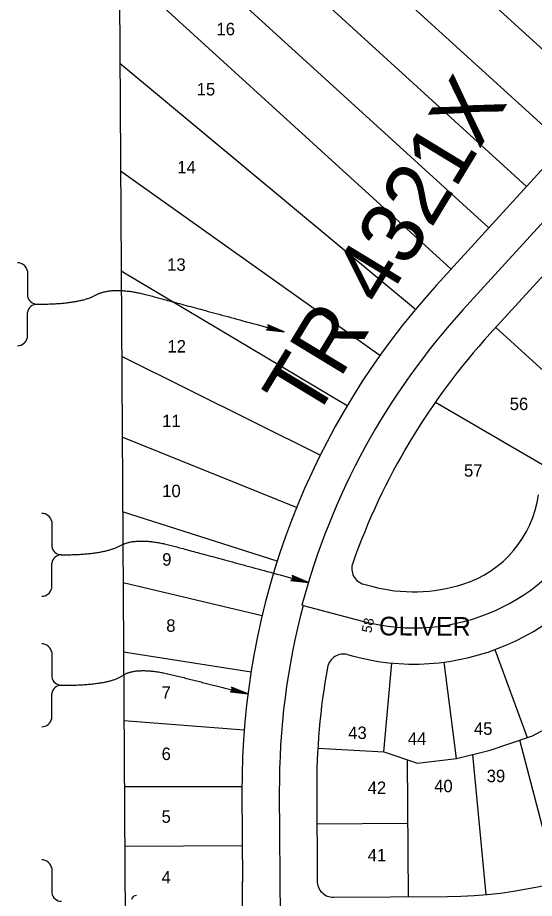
# Model space of a CAD drawing. Extents: x 6387474 to 6390971, y 1972046 to 1973920.
# Drawn here: x 6388992 to 6389408, y 1972544 to 1973251 of the extents above; entities that cross this region are included whole.
import ezdxf

# ---------------------------------------------------------------- set-up
doc = ezdxf.new("R2010")
doc.units = 0
for name, color, linetype in [('1', 7, 'Continuous'), ('2', 7, 'Continuous'), ('3', 7, 'Continuous'), ('4', 7, 'Continuous'), ('7', 7, 'Continuous'), ('8', 7, 'Continuous')]:
    doc.layers.add(name, color=color, linetype=linetype)

msp = doc.modelspace()

# ---------------------------------------------------------------- linework, layer by layer
at = {"layer": '1'}
msp.add_line((6389072.58, 1973552.73), (6389079.62, 1972388), dxfattribs=at)
at = {"layer": '2'}
for p, q in [((6389350.37, 1973016.66), (6389456.72, 1973133.37)), ((6389221.81, 1972779.1), (6389220.84, 1972779.36)), ((6389221.81, 1972779.1), (6389269.5, 1972766.4)), ((6389202.67, 1972629.26), (6389204.12, 1972388.75))]:
    msp.add_line(p, q, dxfattribs=at)
for centre, radius, start, end in [((6389335.56, 1972901.3), 388, 270.34667, 18.92365), ((6389771.66, 1972632.72), 570, 137.65572, 165.09236), ((6389310.66, 1972921.02), 160, 255.09194, 332.86738), ((6389771.66, 1972632.71), 569, 165.09129, 180.34667)]:
    msp.add_arc(centre, radius, start, end, dxfattribs=at)
at = {"layer": '3'}
for p, q in [((6389461.63, 1973182.31), (6389072.67, 1973536.78)), ((6389431.59, 1973148.83), (6389073.04, 1973475.59)), ((6389401.27, 1973115.57), (6389073.41, 1973414.37)), ((6389370.96, 1973082.31), (6389073.78, 1973353.15)), ((6389340.65, 1973049.05), (6389074.15, 1973291.92)), ((6389311.98, 1973016.76), (6389074.62, 1973214.19)), ((6389283.44, 1972979.77), (6389075.15, 1973127.84)), ((6389257.09, 1972939.34), (6389075.63, 1973047.48)), ((6389435.19, 1972948.92), (6389376.6, 1973002.32)), ((6389235.43, 1972899.65), (6389076.05, 1972978.99)), ((6389327.99, 1972942.3), (6389414.18, 1972892.32)), ((6389216.48, 1972857.61), (6389076.44, 1972914.35)), ((6389200.96, 1972814.66), (6389076.8, 1972854.25)), ((6389188.79, 1972770.79), (6389077.15, 1972797.26)), ((6389077.48, 1972741.93), (6389180.01, 1972725.8)), ((6389375.73, 1972743.57), (6389401.65, 1972672.9)), ((6389286.52, 1972661.43), (6389293.16, 1972732.83)), ((6389345.1, 1972656.26), (6389335.04, 1972733.6)), ((6389406.07, 1972674.39), (6389449.77, 1972698.35)), ((6389077.82, 1972686.64), (6389174.5, 1972679.13)), ((6389371.93, 1972662.88), (6389406.07, 1972674.39)), ((6389425.58, 1972556.87), (6389395.79, 1972670.93)), ((6389233.6, 1972664.57), (6389286.52, 1972661.43)), ((6389286.52, 1972661.43), (6389313.75, 1972652.36)), ((6389345.1, 1972656.26), (6389371.93, 1972662.88)), ((6389305.46, 1972655.12), (6389306.13, 1972545.12)), ((6389313.75, 1972652.36), (6389345.1, 1972656.26)), ((6389368.72, 1972546.86), (6389358.18, 1972659.49)), ((6389078.14, 1972633.77), (6389172.66, 1972633.63)), ((6389232.82, 1972603.68), (6389305.77, 1972604.12)), ((6389078.43, 1972585.83), (6389172.92, 1972586.4))]:
    msp.add_line(p, q, dxfattribs=at)
at = {"layer": '4'}
for p, q in [((6389328.93, 1973036.19), (6389435.29, 1973152.9)), ((6389371.8, 1972997.13), (6389418.21, 1973048.05)), ((6389270.51, 1972796.15), (6389276.96, 1972794.43)), ((6389257.52, 1972739.58), (6389262.04, 1972738.38)), ((6389172.67, 1972629.1), (6389173.1, 1972556.84)), ((6389232.67, 1972629.45), (6389233.1, 1972557.68)), ((6389246.18, 1972544.76), (6389337.72, 1972545.31))]:
    msp.add_line(p, q, dxfattribs=at)
for centre, radius, start, end in [((6389771.66, 1972632.72), 599, 137.65605, 180.34667), ((6389335.56, 1972901.3), 356, 270.34667, 18.92365), ((6389771.66, 1972632.72), 541, 137.65572, 160.52995), ((6389323.62, 1972880.02), 88, 287.54705, 352.08944), ((6389310.66, 1972921.02), 189, 253.67626, 332.86738), ((6389273.85, 1972808.71), 13, 160.52995, 255.09194), ((6389310.66, 1972921.02), 131, 255.09194, 287.55198), ((6389254.18, 1972727.02), 13, 75.09194, 169.67106), ((6389771.66, 1972632.71), 539, 169.67106, 180.34667), ((6388172.12, 1972551.26), 1001, 357.80051, 0.34648), ((6389246.1, 1972557.76), 13, 180.34667, 270.34667)]:
    msp.add_arc(centre, radius, start, end, dxfattribs=at)
at = {"layer": '8'}
for p, q in [((6389000.34, 1973047.64), (6389000.34, 1973027.66)), ((6389000.34, 1972994.35), (6389000.34, 1973014.33)), ((6389192.47, 1973000.46), (6389206.51, 1972998.74)), ((6389206.51, 1972998.74), (6389193.52, 1973004.32)), ((6389019.82, 1972846.37), (6389019.82, 1972826.39)), ((6389019.82, 1972793.09), (6389019.82, 1972813.07)), ((6389225.99, 1972797.47), (6389213, 1972803.06)), ((6389211.95, 1972799.19), (6389225.99, 1972797.47)), ((6389019.82, 1972741.6), (6389019.82, 1972721.62)), ((6389163.36, 1972709.58), (6389177.43, 1972708.17)), ((6389177.43, 1972708.17), (6389164.32, 1972713.47)), ((6389019.82, 1972688.32), (6389019.82, 1972708.3)), ((6389019.82, 1972568.13), (6389019.82, 1972548.15))]:
    msp.add_line(p, q, dxfattribs=at)
for points in [[(6389008.23, 1973020.99), (6389009.5, 1973020.99), (6389010.76, 1973021), (6389012, 1973021.02), (6389013.23, 1973021.03), (6389014.45, 1973021.06), (6389015.65, 1973021.09), (6389016.83, 1973021.12), (6389018, 1973021.16), (6389019.16, 1973021.21), (6389020.3, 1973021.26), (6389021.42, 1973021.31), (6389022.54, 1973021.37), (6389023.63, 1973021.44), (6389024.72, 1973021.51), (6389025.79, 1973021.59), (6389026.84, 1973021.67), (6389027.88, 1973021.76), (6389028.9, 1973021.85), (6389029.91, 1973021.95), (6389030.91, 1973022.06), (6389031.89, 1973022.16), (6389032.86, 1973022.28), (6389033.81, 1973022.4), (6389034.75, 1973022.52), (6389035.67, 1973022.65), (6389036.58, 1973022.79), (6389037.48, 1973022.93), (6389038.35, 1973023.08), (6389039.22, 1973023.23), (6389040.07, 1973023.38), (6389040.91, 1973023.55), (6389041.73, 1973023.71), (6389042.54, 1973023.89), (6389043.33, 1973024.07), (6389044.11, 1973024.25), (6389044.87, 1973024.44), (6389045.62, 1973024.63), (6389046.35, 1973024.83), (6389047.07, 1973025.04), (6389047.78, 1973025.25), (6389048.47, 1973025.46), (6389049.15, 1973025.68), (6389049.81, 1973025.91), (6389050.46, 1973026.14), (6389051.09, 1973026.38), (6389051.71, 1973026.62), (6389052.31, 1973026.87), (6389052.9, 1973027.12), (6389053.47, 1973027.38), (6389054.03, 1973027.64), (6389054.58, 1973027.91), (6389055.11, 1973028.18), (6389055.63, 1973028.46), (6389056.14, 1973028.74), (6389056.67, 1973029), (6389057.21, 1973029.26), (6389057.76, 1973029.5), (6389058.32, 1973029.73), (6389058.89, 1973029.95), (6389059.47, 1973030.16), (6389060.07, 1973030.36), (6389060.67, 1973030.55), (6389061.29, 1973030.73), (6389061.92, 1973030.9), (6389062.56, 1973031.05), (6389063.21, 1973031.2), (6389063.87, 1973031.33), (6389064.55, 1973031.45), (6389065.23, 1973031.56), (6389065.93, 1973031.66), (6389066.64, 1973031.75), (6389067.36, 1973031.83), (6389068.09, 1973031.9), (6389068.83, 1973031.95), (6389069.58, 1973032), (6389070.35, 1973032.03), (6389071.12, 1973032.06), (6389071.91, 1973032.07), (6389072.71, 1973032.07), (6389073.52, 1973032.06), (6389074.34, 1973032.04), (6389075.18, 1973032.01), (6389076.02, 1973031.97), (6389076.88, 1973031.91), (6389077.74, 1973031.85), (6389078.62, 1973031.77), (6389079.51, 1973031.68), (6389080.41, 1973031.59), (6389081.33, 1973031.48), (6389082.25, 1973031.36), (6389083.18, 1973031.23), (6389084.13, 1973031.09), (6389085.09, 1973030.93), (6389086.06, 1973030.77), (6389087.04, 1973030.59), (6389088.03, 1973030.41), (6389089.04, 1973030.21), (6389090.05, 1973030), (6389091.08, 1973029.79), (6389092.11, 1973029.56)], [(6389092.11, 1973029.56), (6389093.16, 1973029.32), (6389094.22, 1973029.06), (6389095.29, 1973028.8), (6389096.38, 1973028.53), (6389097.47, 1973028.24), (6389098.58, 1973027.95), (6389099.71, 1973027.64), (6389100.87, 1973027.33), (6389102.07, 1973027), (6389103.3, 1973026.67), (6389104.57, 1973026.32), (6389105.87, 1973025.97), (6389107.21, 1973025.61), (6389108.59, 1973025.23), (6389109.99, 1973024.85), (6389111.44, 1973024.46), (6389112.91, 1973024.06), (6389114.43, 1973023.65), (6389115.97, 1973023.23), (6389117.56, 1973022.8), (6389119.18, 1973022.37), (6389120.83, 1973021.92), (6389122.51, 1973021.46), (6389124.24, 1973021), (6389125.99, 1973020.52), (6389127.79, 1973020.04), (6389129.61, 1973019.54), (6389131.48, 1973019.04), (6389133.37, 1973018.52), (6389135.3, 1973018), (6389137.27, 1973017.47), (6389139.27, 1973016.93), (6389141.31, 1973016.37), (6389143.38, 1973015.81), (6389145.49, 1973015.24), (6389147.63, 1973014.66), (6389149.8, 1973014.08), (6389152.01, 1973013.48), (6389154.26, 1973012.87), (6389156.54, 1973012.25), (6389158.86, 1973011.62), (6389161.21, 1973010.99), (6389163.59, 1973010.34), (6389166.01, 1973009.69), (6389168.47, 1973009.02), (6389170.96, 1973008.35), (6389173.48, 1973007.67), (6389176.05, 1973006.97), (6389178.64, 1973006.27), (6389181.27, 1973005.56), (6389183.93, 1973004.84), (6389186.63, 1973004.11), (6389189.37, 1973003.37), (6389192.14, 1973002.62), (6389194.94, 1973001.86), (6389197.78, 1973001.09), (6389200.66, 1973000.31), (6389203.57, 1972999.53), (6389206.51, 1972998.73)], [(6389027.71, 1972819.73), (6389028.98, 1972819.73), (6389030.24, 1972819.74), (6389031.48, 1972819.75), (6389032.71, 1972819.77), (6389033.92, 1972819.79), (6389035.12, 1972819.82), (6389036.31, 1972819.86), (6389037.48, 1972819.9), (6389038.63, 1972819.94), (6389039.77, 1972819.99), (6389040.9, 1972820.05), (6389042.01, 1972820.11), (6389043.11, 1972820.18), (6389044.19, 1972820.25), (6389045.26, 1972820.32), (6389046.32, 1972820.41), (6389047.36, 1972820.49), (6389048.38, 1972820.59), (6389049.39, 1972820.69), (6389050.39, 1972820.79), (6389051.37, 1972820.9), (6389052.34, 1972821.01), (6389053.29, 1972821.13), (6389054.23, 1972821.26), (6389055.15, 1972821.39), (6389056.06, 1972821.52), (6389056.95, 1972821.66), (6389057.83, 1972821.81), (6389058.7, 1972821.96), (6389059.55, 1972822.12), (6389060.38, 1972822.28), (6389061.21, 1972822.45), (6389062.01, 1972822.62), (6389062.81, 1972822.8), (6389063.58, 1972822.98), (6389064.35, 1972823.17), (6389065.1, 1972823.37), (6389065.83, 1972823.57), (6389066.55, 1972823.77), (6389067.26, 1972823.98), (6389067.95, 1972824.2), (6389068.62, 1972824.42), (6389069.28, 1972824.64), (6389069.93, 1972824.87), (6389070.57, 1972825.11), (6389071.18, 1972825.35), (6389071.79, 1972825.6), (6389072.38, 1972825.85), (6389072.95, 1972826.11), (6389073.51, 1972826.37), (6389074.06, 1972826.64), (6389074.59, 1972826.92), (6389075.1, 1972827.19), (6389075.62, 1972827.47), (6389076.15, 1972827.74), (6389076.68, 1972827.99), (6389077.23, 1972828.23), (6389077.79, 1972828.47), (6389078.37, 1972828.69), (6389078.95, 1972828.9), (6389079.54, 1972829.1), (6389080.15, 1972829.29), (6389080.77, 1972829.46), (6389081.4, 1972829.63), (6389082.04, 1972829.78), (6389082.69, 1972829.93), (6389083.35, 1972830.06), (6389084.02, 1972830.18), (6389084.71, 1972830.3), (6389085.41, 1972830.4), (6389086.11, 1972830.49), (6389086.83, 1972830.56), (6389087.56, 1972830.63), (6389088.31, 1972830.69), (6389089.06, 1972830.73), (6389089.82, 1972830.77), (6389090.6, 1972830.79), (6389091.39, 1972830.8), (6389092.19, 1972830.8), (6389093, 1972830.79), (6389093.82, 1972830.77), (6389094.65, 1972830.74), (6389095.5, 1972830.7), (6389096.35, 1972830.65), (6389097.22, 1972830.58), (6389098.1, 1972830.51), (6389098.99, 1972830.42), (6389099.89, 1972830.32), (6389100.8, 1972830.21), (6389101.73, 1972830.09), (6389102.66, 1972829.96), (6389103.61, 1972829.82), (6389104.57, 1972829.67), (6389105.54, 1972829.5), (6389106.52, 1972829.33), (6389107.51, 1972829.14), (6389108.51, 1972828.95), (6389109.53, 1972828.74), (6389110.55, 1972828.52), (6389111.59, 1972828.29)], [(6389111.59, 1972828.29), (6389112.64, 1972828.05), (6389113.7, 1972827.8), (6389114.77, 1972827.53), (6389115.85, 1972827.26), (6389116.95, 1972826.98), (6389118.05, 1972826.68), (6389119.18, 1972826.37), (6389120.35, 1972826.06), (6389121.55, 1972825.73), (6389122.78, 1972825.4), (6389124.05, 1972825.06), (6389125.35, 1972824.7), (6389126.69, 1972824.34), (6389128.06, 1972823.97), (6389129.47, 1972823.59), (6389130.91, 1972823.2), (6389132.39, 1972822.8), (6389133.9, 1972822.39), (6389135.45, 1972821.97), (6389137.03, 1972821.54), (6389138.65, 1972821.1), (6389140.3, 1972820.65), (6389141.99, 1972820.2), (6389143.71, 1972819.73), (6389145.47, 1972819.25), (6389147.26, 1972818.77), (6389149.09, 1972818.27), (6389150.95, 1972817.77), (6389152.85, 1972817.26), (6389154.78, 1972816.73), (6389156.75, 1972816.2), (6389158.75, 1972815.66), (6389160.79, 1972815.11), (6389162.86, 1972814.55), (6389164.96, 1972813.98), (6389167.1, 1972813.4), (6389169.28, 1972812.81), (6389171.49, 1972812.21), (6389173.74, 1972811.6), (6389176.02, 1972810.99), (6389178.33, 1972810.36), (6389180.68, 1972809.72), (6389183.07, 1972809.08), (6389185.49, 1972808.42), (6389187.95, 1972807.76), (6389190.44, 1972807.08), (6389192.96, 1972806.4), (6389195.52, 1972805.71), (6389198.12, 1972805.01), (6389200.75, 1972804.29), (6389203.41, 1972803.57), (6389206.11, 1972802.84), (6389208.85, 1972802.1), (6389211.62, 1972801.35), (6389214.42, 1972800.59), (6389217.26, 1972799.83), (6389220.13, 1972799.05), (6389223.04, 1972798.26), (6389225.99, 1972797.46)], [(6389027.71, 1972714.96), (6389029.13, 1972714.96), (6389030.54, 1972714.97), (6389031.93, 1972714.98), (6389033.29, 1972715), (6389034.64, 1972715.03), (6389035.97, 1972715.06), (6389037.28, 1972715.09), (6389038.57, 1972715.14), (6389039.85, 1972715.18), (6389041.1, 1972715.24), (6389042.33, 1972715.3), (6389043.55, 1972715.36), (6389044.75, 1972715.43), (6389045.92, 1972715.51), (6389047.08, 1972715.59), (6389048.22, 1972715.67), (6389049.34, 1972715.77), (6389050.44, 1972715.87), (6389051.52, 1972715.97), (6389052.58, 1972716.08), (6389053.63, 1972716.19), (6389054.65, 1972716.31), (6389055.66, 1972716.44), (6389056.64, 1972716.57), (6389057.61, 1972716.71), (6389058.56, 1972716.85), (6389059.49, 1972717), (6389060.4, 1972717.16), (6389061.29, 1972717.32), (6389062.16, 1972717.48), (6389063.01, 1972717.65), (6389063.85, 1972717.83), (6389064.66, 1972718.01), (6389065.45, 1972718.2), (6389066.23, 1972718.39), (6389066.99, 1972718.59), (6389067.73, 1972718.8), (6389068.45, 1972719.01), (6389069.15, 1972719.22), (6389069.83, 1972719.45), (6389070.49, 1972719.67), (6389071.13, 1972719.91), (6389071.75, 1972720.14), (6389072.36, 1972720.39), (6389072.94, 1972720.64), (6389073.51, 1972720.89), (6389074.06, 1972721.16), (6389074.59, 1972721.42), (6389075.1, 1972721.69), (6389075.59, 1972721.97), (6389076.06, 1972722.26), (6389076.51, 1972722.54), (6389076.94, 1972722.84), (6389077.37, 1972723.13), (6389077.82, 1972723.41), (6389078.28, 1972723.68), (6389078.75, 1972723.94), (6389079.24, 1972724.18), (6389079.74, 1972724.42), (6389080.26, 1972724.64), (6389080.8, 1972724.85), (6389081.34, 1972725.06), (6389081.91, 1972725.24), (6389082.48, 1972725.42), (6389083.07, 1972725.59), (6389083.68, 1972725.74), (6389084.3, 1972725.89), (6389084.94, 1972726.02), (6389085.59, 1972726.14), (6389086.25, 1972726.25), (6389086.93, 1972726.35), (6389087.62, 1972726.44), (6389088.33, 1972726.51), (6389089.06, 1972726.58), (6389089.79, 1972726.63), (6389090.55, 1972726.67), (6389091.31, 1972726.7), (6389092.1, 1972726.72), (6389092.89, 1972726.73), (6389093.7, 1972726.72), (6389094.53, 1972726.71), (6389095.37, 1972726.68), (6389096.23, 1972726.64), (6389097.1, 1972726.59), (6389097.98, 1972726.53), (6389098.88, 1972726.46), (6389099.79, 1972726.37), (6389100.72, 1972726.28), (6389101.66, 1972726.17), (6389102.62, 1972726.05), (6389103.59, 1972725.92), (6389104.58, 1972725.78), (6389105.58, 1972725.63), (6389106.6, 1972725.47), (6389107.63, 1972725.29), (6389108.68, 1972725.1), (6389109.74, 1972724.91), (6389110.81, 1972724.7), (6389111.9, 1972724.48), (6389113, 1972724.25)], [(6389113, 1972724.25), (6389114.12, 1972724), (6389115.26, 1972723.75), (6389116.4, 1972723.48), (6389117.57, 1972723.2), (6389118.74, 1972722.91), (6389119.94, 1972722.61), (6389121.13, 1972722.31), (6389122.32, 1972722.01), (6389123.51, 1972721.7), (6389124.7, 1972721.4), (6389125.88, 1972721.1), (6389127.05, 1972720.8), (6389128.22, 1972720.5), (6389129.39, 1972720.21), (6389130.55, 1972719.91), (6389131.71, 1972719.62), (6389132.87, 1972719.33), (6389134.01, 1972719.03), (6389135.16, 1972718.74), (6389136.3, 1972718.46), (6389137.44, 1972718.17), (6389138.57, 1972717.88), (6389139.7, 1972717.6), (6389140.82, 1972717.31), (6389141.94, 1972717.03), (6389143.06, 1972716.75), (6389144.17, 1972716.47), (6389145.27, 1972716.19), (6389146.38, 1972715.91), (6389147.47, 1972715.64), (6389148.57, 1972715.36), (6389149.66, 1972715.09), (6389150.74, 1972714.81), (6389151.82, 1972714.54), (6389152.9, 1972714.27), (6389153.97, 1972714), (6389155.04, 1972713.74), (6389156.1, 1972713.47), (6389157.16, 1972713.21), (6389158.21, 1972712.94), (6389159.26, 1972712.68), (6389160.31, 1972712.42), (6389161.35, 1972712.16), (6389162.39, 1972711.9), (6389163.42, 1972711.64), (6389164.45, 1972711.39), (6389165.48, 1972711.13), (6389166.5, 1972710.88), (6389167.51, 1972710.62), (6389168.52, 1972710.37), (6389169.53, 1972710.12), (6389170.53, 1972709.88), (6389171.53, 1972709.63), (6389172.53, 1972709.38), (6389173.52, 1972709.14), (6389174.5, 1972708.89), (6389175.48, 1972708.65), (6389176.46, 1972708.41), (6389177.43, 1972708.17)]]:
    msp.add_lwpolyline(points, dxfattribs=at)
for points in [[(6389206.51, 1972998.74), (6389192.98, 1973000.74), (6389192.47, 1973000.46)], [(6389206.51, 1972998.74), (6389193.41, 1973001.12), (6389192.98, 1973000.74)], [(6389206.51, 1972998.74), (6389193.75, 1973001.59), (6389193.41, 1973001.12)], [(6389193.52, 1973004.32), (6389193.82, 1973003.83), (6389206.51, 1972998.74)], [(6389193.96, 1973002.13), (6389193.75, 1973001.59), (6389206.51, 1972998.74)], [(6389193.82, 1973003.83), (6389194, 1973003.28), (6389206.51, 1972998.74)], [(6389194.05, 1973002.7), (6389193.96, 1973002.13), (6389206.51, 1972998.74)], [(6389194, 1973003.28), (6389194.05, 1973002.7), (6389206.51, 1972998.74)], [(6389213, 1972803.06), (6389213.3, 1972802.56), (6389225.99, 1972797.47)], [(6389213.3, 1972802.56), (6389213.48, 1972802.01), (6389225.99, 1972797.47)], [(6389213.48, 1972802.01), (6389213.52, 1972801.44), (6389225.99, 1972797.47)], [(6389225.99, 1972797.47), (6389212.46, 1972799.47), (6389211.95, 1972799.19)], [(6389225.99, 1972797.47), (6389212.89, 1972799.85), (6389212.46, 1972799.47)], [(6389225.99, 1972797.47), (6389213.22, 1972800.33), (6389212.89, 1972799.85)], [(6389213.44, 1972800.86), (6389213.22, 1972800.33), (6389225.99, 1972797.47)], [(6389213.52, 1972801.44), (6389213.44, 1972800.86), (6389225.99, 1972797.47)], [(6389177.43, 1972708.17), (6389163.86, 1972709.87), (6389163.36, 1972709.58)], [(6389177.43, 1972708.17), (6389164.29, 1972710.26), (6389163.86, 1972709.87)], [(6389177.43, 1972708.17), (6389164.61, 1972710.74), (6389164.29, 1972710.26)], [(6389164.32, 1972713.47), (6389164.63, 1972712.98), (6389177.43, 1972708.17)], [(6389164.81, 1972711.28), (6389164.61, 1972710.74), (6389177.43, 1972708.17)], [(6389164.63, 1972712.98), (6389164.82, 1972712.43), (6389177.43, 1972708.17)], [(6389164.88, 1972711.86), (6389164.81, 1972711.28), (6389177.43, 1972708.17)], [(6389164.82, 1972712.43), (6389164.88, 1972711.86), (6389177.43, 1972708.17)]]:
    msp.add_lwpolyline(points, close=True, dxfattribs=at)
for centre, radius, start, end in [((6388992.46, 1973046.3), 8, 9.61952, 90), ((6389008.23, 1973029), 8, 189.61952, 270), ((6389008.23, 1973013), 8, 90, 170.38048), ((6389191.55, 1973002.78), 2.5, 291.73131, 37.99152), ((6388992.46, 1972995.69), 8, 270, 350.38048), ((6389011.93, 1972845.04), 8, 9.61952, 90), ((6389027.71, 1972827.73), 8, 189.61952, 270), ((6389027.71, 1972811.73), 8, 90, 170.38048), ((6389211.03, 1972801.52), 2.5, 291.73131, 37.99152), ((6389011.93, 1972794.42), 8, 270, 350.38048), ((6389011.93, 1972740.27), 8, 9.61952, 90), ((6389027.71, 1972722.96), 8, 189.61952, 270), ((6389027.71, 1972706.96), 8, 90, 170.38048), ((6389162.38, 1972711.88), 2.5, 293.0279, 39.28811), ((6389011.93, 1972689.65), 8, 270, 350.38048), ((6389011.93, 1972566.8), 8, 9.61952, 90), ((6389027.71, 1972549.49), 8, 189.61952, 270), ((6389087.67, 1972542.45), 3.68, 86.25389, 172.99909)]:
    msp.add_arc(centre, radius, start, end, dxfattribs=at)

# ---------------------------------------------------------------- texts
at = {"layer": '1'}
msp.add_text('TR 4321X', height=50, rotation=58.72918, dxfattribs=at).set_placement((6389230.06, 1972925.59))
at = {"layer": '2'}
msp.add_text('OLIVER', height=15, rotation=359.71156, dxfattribs=at).set_placement((6389282.79, 1972755.05))
at = {"layer": '4'}
msp.add_text('58', height=8, rotation=78.59358, dxfattribs=at).set_placement((6389276.49, 1972756.52))
at = {"layer": '7'}
for s, p in [('16', (6389152.15, 1973236.98)), ('15', (6389136.29, 1973188.64)), ('14', (6389120.72, 1973126.01)), ('13', (6389112.57, 1973047.82)), ('12', (6389112.81, 1972982.2)), ('56', (6389387.7, 1972935.96)), ('11', (6389108.58, 1972922.28)), ('57', (6389350.99, 1972882.53)), ('10', (6389108.58, 1972866.05)), ('9', (6389108.58, 1972811)), ('8', (6389111.85, 1972757.94)), ('7', (6389108.11, 1972704.12)), ('43', (6389258, 1972671.83)), ('45', (6389358.97, 1972675.15)), ('44', (6389305.88, 1972667.08)), ('6', (6389108.11, 1972654.92)), ('39', (6389369.24, 1972637.14)), ('40', (6389327.05, 1972629.07)), ('42', (6389273.64, 1972627.7)), ('5', (6389108.11, 1972604.55)), ('41', (6389273.64, 1972573.6)), ('4', (6389108.11, 1972555.79))]:
    msp.add_text(s, height=10, dxfattribs=at).set_placement(p)

doc.saveas('drawing.dxf')
